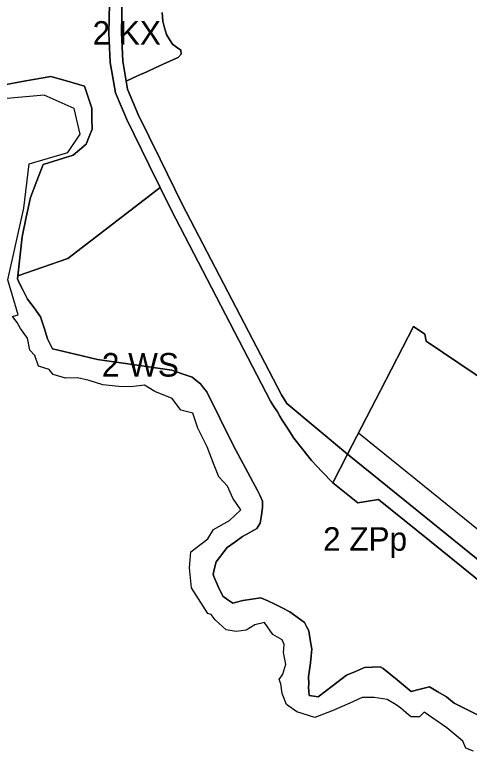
# Model space of a CAD drawing. Extents: x -295551 to -293631, y 22633 to 24461.
# Drawn here: x -294907.1 to -294617.6, y 22699.5 to 23168.5 of the extents above; entities that cross this region are included whole.
import ezdxf

# ---------------------------------------------------------------- set-up
doc = ezdxf.new("R2010")
doc.units = 0
for name, color, linetype in [('linie_rozgraniczajace', 7, 'Continuous'), ('linie_zabudowy_nieprzekraczalne', 7, 'Continuous'), ('oznaczenia_przeznaczen', 7, 'Continuous')]:
    doc.layers.add(name, color=color, linetype=linetype)

msp = doc.modelspace()

# ---------------------------------------------------------------- linework, layer by layer
at = {"layer": 'linie_rozgraniczajace'}
for points in [[(-294846.188, 23203.99), (-294847.114, 23156.82), (-294846.679, 23147.513), (-294846.244, 23138.206), (-294844.623, 23128.5), (-294843.003, 23118.793), (-294839.334, 23110.255), (-294835.665, 23101.717), (-294821.625, 23073.051), (-294814.5, 23058.503), (-294843.899, 23035.888), (-294873.298, 23013.272), (-294889.262, 23007.782), (-294905.227, 23002.292), (-294903.939, 23013.774), (-294902.438, 23027.157), (-294899.748, 23039.665), (-294897.058, 23052.173), (-294892.974, 23062.676), (-294888.89, 23073.18), (-294879.345, 23076.115), (-294869.8, 23079.05), (-294865.755, 23082.555), (-294861.71, 23086.06), (-294859.745, 23090.895), (-294857.78, 23095.73), (-294857.91, 23102.35), (-294858.04, 23108.97), (-294860.375, 23115.99), (-294862.71, 23123.01), (-294873.405, 23126.15), (-294884.1, 23129.29), (-294900.019, 23126.357), (-294915.939, 23123.424)], [(-294838.187, 23203.997), (-294839.111, 23156.928), (-294838.693, 23147.992), (-294838.275, 23139.055), (-294836.773, 23130.059), (-294836.139, 23126.261), (-294835.271, 23121.064), (-294831.832, 23113.061), (-294828.393, 23105.058), (-294814.417, 23076.524), (-294800.442, 23047.989), (-294768.852, 22987.178), (-294737.262, 22926.367), (-294733.747, 22920.931), (-294714.441, 22904.781), (-294695.135, 22888.631), (-294704.498, 22870.482), (-294711.278, 22877.528), (-294718.058, 22884.574), (-294723.688, 22891.674), (-294729.317, 22898.774), (-294733.021, 22904.515), (-294736.725, 22910.257), (-294738.267, 22912.914), (-294739.808, 22915.571), (-294741.997, 22918.957), (-294744.186, 22922.342), (-294775.885, 22983.364), (-294807.514, 23044.245), (-294814.5, 23058.503), (-294821.625, 23073.051), (-294835.665, 23101.717), (-294839.334, 23110.255), (-294843.003, 23118.793), (-294844.623, 23128.5), (-294846.244, 23138.206), (-294846.679, 23147.513), (-294847.114, 23156.82), (-294846.188, 23203.99)], [(-294813.115, 23169.882), (-294812.975, 23167.207), (-294812.836, 23164.531), (-294811.65, 23160.195), (-294810.464, 23155.858), (-294808.542, 23152.831), (-294806.619, 23149.805), (-294803.974, 23147.887), (-294801.329, 23145.969), (-294801.05, 23143.396), (-294802.988, 23141.332), (-294810.276, 23138.019), (-294817.563, 23134.705), (-294823.041, 23132.217), (-294828.519, 23129.729), (-294836.139, 23126.261), (-294836.773, 23130.059), (-294838.275, 23139.055), (-294838.693, 23147.992), (-294839.111, 23156.928), (-294838.187, 23203.997)], [(-294836.139, 23126.261), (-294828.519, 23129.729), (-294823.041, 23132.217), (-294817.563, 23134.705), (-294810.276, 23138.019), (-294802.988, 23141.332), (-294801.05, 23143.396), (-294801.329, 23145.969), (-294803.974, 23147.887), (-294806.619, 23149.805), (-294808.542, 23152.831), (-294810.464, 23155.858), (-294811.65, 23160.195), (-294812.836, 23164.531), (-294812.975, 23167.207), (-294813.115, 23169.882)], [(-294915.939, 23123.424), (-294900.019, 23126.357), (-294884.1, 23129.29), (-294873.405, 23126.15), (-294862.71, 23123.01), (-294860.375, 23115.99), (-294858.04, 23108.97), (-294857.91, 23102.35), (-294857.78, 23095.73), (-294859.745, 23090.895), (-294861.71, 23086.06), (-294865.755, 23082.555), (-294869.8, 23079.05), (-294879.345, 23076.115), (-294888.89, 23073.18), (-294892.974, 23062.676), (-294897.058, 23052.173), (-294899.748, 23039.665), (-294902.438, 23027.157), (-294903.939, 23013.774), (-294905.227, 23002.292), (-294905.44, 23000.39), (-294903.977, 22997.43), (-294902.21, 22993.855), (-294898.98, 22987.32), (-294894.79, 22981.765), (-294890.6, 22976.21), (-294888.439, 22969.179), (-294886.277, 22962.148), (-294883.06, 22955.73), (-294868.7, 22952.385), (-294854.34, 22949.04), (-294830.65, 22945.585), (-294806.96, 22942.13), (-294800.555, 22939.9), (-294794.15, 22937.67), (-294791.515, 22935.59), (-294788.88, 22933.51), (-294786.785, 22930.915), (-294784.69, 22928.32), (-294776.19, 22911.185), (-294767.69, 22894.05), (-294760.07, 22879.8), (-294752.45, 22865.55), (-294750.85, 22862.16), (-294749.25, 22858.77), (-294749.23, 22854.75), (-294749.995, 22849.785), (-294750.76, 22844.82), (-294751.855, 22843.085), (-294752.95, 22841.35), (-294757.46, 22838.79), (-294761.97, 22836.23), (-294766.905, 22832.695), (-294771.84, 22829.16), (-294778.85, 22820.02), (-294779.78, 22816.18), (-294780.71, 22812.34), (-294780.345, 22810.727), (-294777.448, 22804.508), (-294774.55, 22798.29), (-294771.335, 22795.995), (-294768.12, 22793.7), (-294765.005, 22794.545), (-294761.89, 22795.39), (-294756.175, 22796.305), (-294750.46, 22797.22), (-294746, 22795.225), (-294741.54, 22793.23), (-294736.765, 22790.795), (-294731.99, 22788.36), (-294727.325, 22784.965), (-294722.66, 22781.57), (-294721.22, 22778.89), (-294719.78, 22776.21), (-294718.85, 22770.38), (-294717.92, 22764.55), (-294718.345, 22760.185), (-294718.77, 22755.82), (-294719.41, 22751.395), (-294720.05, 22746.97), (-294719.85, 22742.36), (-294719.93, 22740.2), (-294719.714, 22737.648), (-294719.497, 22735.096), (-294716.703, 22734.622), (-294713.908, 22734.149), (-294704.911, 22741.015), (-294695.913, 22747.881), (-294690.137, 22750.37), (-294684.36, 22752.86), (-294679.35, 22753.025), (-294674.34, 22753.19), (-294672.45, 22752.17), (-294663.569, 22744.904), (-294654.689, 22737.638), (-294648.963, 22739.099), (-294643.015, 22740.427), (-294637.542, 22737.268), (-294632.07, 22734.11)], [(-294580.627, 22917.648), (-294592.034, 22925.154), (-294603.44, 22932.66), (-294624.305, 22946.67), (-294645.17, 22960.68), (-294646.01, 22965.09), (-294653.196, 22969.926), (-294674.166, 22929.279), (-294695.135, 22888.631), (-294714.441, 22904.781), (-294733.747, 22920.931), (-294737.262, 22926.367), (-294768.852, 22987.178), (-294800.442, 23047.989), (-294814.417, 23076.524), (-294828.393, 23105.058), (-294831.832, 23113.061), (-294835.271, 23121.064), (-294836.139, 23126.261)], [(-294795.75, 22816.28), (-294795.03, 22826.54), (-294784.14, 22834.73), (-294780.45, 22840.76), (-294770.22, 22846.34), (-294763.01, 22853.17), (-294768.15, 22860.7), (-294771.68, 22868.27), (-294777.17, 22874.21), (-294780.19, 22881.75), (-294784.46, 22893.34), (-294790.49, 22905.33), (-294793.78, 22914.69), (-294801.26, 22916.69), (-294806.86, 22924.14), (-294817.94, 22928.63), (-294824.45, 22932.62), (-294833.23, 22931.49), (-294840.8, 22931.7), (-294850.99, 22932.74), (-294859.74, 22935.67), (-294867.23, 22937.2), (-294874.74, 22937.12), (-294882.52, 22939.39), (-294885.09, 22942.51), (-294891.96, 22944.73), (-294894.35, 22951.41), (-294897.56, 22954.97), (-294898.99, 22962.57), (-294903.38, 22968.8), (-294905.51, 22972.45), (-294908.55, 22976.432), (-294904.872, 22977.352), (-294911.516, 22999.745), (-294901.211, 23045.387), (-294897.837, 23073.676), (-294873.213, 23080.785), (-294865.396, 23092.514), (-294869.305, 23108.864), (-294888.456, 23117.395), (-294956.855, 23111.144)], [(-294905.44, 23000.39), (-294905.227, 23002.292), (-294889.262, 23007.782), (-294873.298, 23013.272), (-294843.899, 23035.888), (-294814.5, 23058.503), (-294807.514, 23044.245), (-294775.885, 22983.364), (-294744.186, 22922.342), (-294741.997, 22918.957), (-294739.808, 22915.571), (-294738.267, 22912.914), (-294736.725, 22910.257), (-294733.021, 22904.515), (-294729.317, 22898.774), (-294723.688, 22891.674), (-294718.058, 22884.574), (-294711.278, 22877.528), (-294704.498, 22870.482), (-294688.617, 22857.644), (-294675.442, 22859.853), (-294642.805, 22833.469), (-294610.167, 22807.084)], [(-294679.35, 22753.025), (-294684.36, 22752.86), (-294690.137, 22750.37), (-294695.913, 22747.881), (-294704.911, 22741.015), (-294713.908, 22734.149), (-294716.703, 22734.622), (-294719.497, 22735.096), (-294719.714, 22737.648), (-294719.93, 22740.2), (-294719.85, 22742.36), (-294720.05, 22746.97), (-294719.41, 22751.395), (-294718.77, 22755.82), (-294718.345, 22760.185), (-294717.92, 22764.55), (-294718.85, 22770.38), (-294719.78, 22776.21), (-294721.22, 22778.89), (-294722.66, 22781.57), (-294727.325, 22784.965), (-294731.99, 22788.36), (-294736.765, 22790.795), (-294741.54, 22793.23), (-294746, 22795.225), (-294750.46, 22797.22), (-294756.175, 22796.305), (-294761.89, 22795.39), (-294765.005, 22794.545), (-294768.12, 22793.7), (-294771.335, 22795.995), (-294774.55, 22798.29), (-294777.448, 22804.508), (-294780.345, 22810.727), (-294780.71, 22812.34), (-294779.78, 22816.18), (-294778.85, 22820.02), (-294771.84, 22829.16), (-294766.905, 22832.695), (-294761.97, 22836.23), (-294757.46, 22838.79), (-294752.95, 22841.35), (-294751.855, 22843.085), (-294750.76, 22844.82), (-294749.995, 22849.785), (-294749.23, 22854.75), (-294749.25, 22858.77), (-294750.85, 22862.16), (-294752.45, 22865.55), (-294760.07, 22879.8), (-294767.69, 22894.05), (-294776.19, 22911.185), (-294784.69, 22928.32), (-294786.785, 22930.915), (-294788.88, 22933.51), (-294791.515, 22935.59), (-294794.15, 22937.67), (-294800.555, 22939.9), (-294806.96, 22942.13), (-294830.65, 22945.585), (-294854.34, 22949.04), (-294868.7, 22952.385), (-294883.06, 22955.73), (-294886.277, 22962.148), (-294888.439, 22969.179), (-294890.6, 22976.21), (-294894.79, 22981.765), (-294898.98, 22987.32), (-294902.21, 22993.855), (-294903.977, 22997.43), (-294905.44, 23000.39)], [(-294604.173, 22815.097), (-294649.654, 22851.864), (-294695.135, 22888.631), (-294674.166, 22929.279), (-294653.196, 22969.926), (-294646.01, 22965.09), (-294645.17, 22960.68), (-294624.305, 22946.67), (-294603.44, 22932.66)], [(-294610.167, 22807.084), (-294642.805, 22833.469), (-294675.442, 22859.853), (-294688.617, 22857.644), (-294704.498, 22870.482), (-294695.135, 22888.631), (-294649.654, 22851.864), (-294604.173, 22815.097)], [(-294614.93, 22699.48), (-294619.87, 22701.36), (-294621.64, 22706), (-294632.01, 22714.48), (-294646.27, 22724.31), (-294649.42, 22721.39), (-294654.65, 22721.33), (-294656.34, 22722.73), (-294661.28, 22726.9), (-294664.13, 22728.97), (-294669.98, 22732.43), (-294678.12, 22733.78), (-294685.86, 22733.75), (-294693.68, 22730.05), (-294704.88, 22725.17), (-294716.03, 22721.02), (-294727.45, 22724.49), (-294733.94, 22729.36), (-294736.69, 22736.29), (-294737.58, 22742.46), (-294738.7, 22745.22), (-294736.28, 22748.61), (-294734.42, 22754.87), (-294736.01, 22762.41), (-294735.41, 22767.49), (-294736.76, 22770.49), (-294742.66, 22773.92), (-294748.06, 22781.5), (-294754.23, 22780.05), (-294759.68, 22776.52), (-294766.13, 22775.76), (-294772.44, 22776.74), (-294779.52, 22783.27), (-294782.03, 22786.49), (-294784.04, 22787.19), (-294794.5, 22803.66), (-294795.75, 22816.28)], [(-294608.562, 22720.865), (-294617.92, 22725.475), (-294627.278, 22730.085), (-294629.674, 22732.098), (-294632.07, 22734.11), (-294637.542, 22737.268), (-294643.015, 22740.427), (-294648.963, 22739.099), (-294654.689, 22737.638), (-294663.569, 22744.904), (-294672.45, 22752.17), (-294674.34, 22753.19), (-294679.35, 22753.025)], [(-294632.07, 22734.11), (-294629.674, 22732.098), (-294627.278, 22730.085), (-294617.92, 22725.475), (-294608.562, 22720.865)]]:
    msp.add_lwpolyline(points, dxfattribs=at)
at = {"layer": 'linie_zabudowy_nieprzekraczalne'}
msp.add_lwpolyline([(-294688.113, 22902.243), (-294688.113, 22902.243), (-294595.181, 22827.116)], dxfattribs=at)

# ---------------------------------------------------------------- texts
at = {"layer": 'oznaczenia_przeznaczen'}
for s, p in [('2 KX', (-294857.5, 23149.428)), ('2 WS', (-294851.584, 22938.085)), ('2 ZPp', (-294710.732, 22827.182))]:
    msp.add_text(s, height=15, dxfattribs=at).set_placement(p)

doc.saveas('drawing.dxf')
